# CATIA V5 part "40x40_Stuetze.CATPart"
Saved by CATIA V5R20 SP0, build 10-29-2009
Part number: 40x40_Stuetze
Nomenclature: P40L_N8_I
Source: Unknown
Bounding box of the stored display mesh (mm): x -20 to 20, y -20 to 20, z -150 to 50
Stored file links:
  C:\Users\Andi\Desktop\Offene Projekte\Plasmacutter\Rahmen\40x40_Stuetze.CATPart
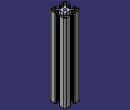
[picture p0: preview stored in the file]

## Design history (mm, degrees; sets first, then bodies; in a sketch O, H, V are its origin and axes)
Set1
  Sketch1 on face of Solid1, origin (0, 0, 150), H (1, 0, 0), V (0, 1, 0)
    projected arc E1 centre (-18.5, 5.5) radius 1.5 from (-20, 5.5) to (-18.5, 4) ccw from edge [face of Solid1 | face of Solid1]
    projected line E2 (-16.5, 4) -> (-18.5, 4) from edge [face of Solid1 | face of Solid1]
    projected arc E3 centre (-16.5, 5) radius 1 from (-16.5, 4) to (-15.5, 5) ccw from edge [face of Solid1 | face of Solid1]
    projected line E4 (-15.5, 6.5) -> (-15.5, 5) from edge [face of Solid1 | face of Solid1]
    projected arc E5 centre (-16, 6.5) radius 0.5 from (-15.5, 6.5) to (-16, 7) ccw from edge [face of Solid1 | face of Solid1]
    projected line E6 (-17.5, 7) -> (-16, 7) from edge [face of Solid1 | face of Solid1]
    projected arc E7 centre (-17.5, 7.5) radius 0.5 from (-18, 7.5) to (-17.5, 7) ccw from edge [face of Solid1 | face of Solid1]
    projected arc E8 centre (-15.5, 7.5) radius 2.5 from (-15.5, 10) to (-18, 7.5) ccw from edge [face of Solid1 | face of Solid1]
    projected line E9 (-14.1924, 10) -> (-15.5, 10) from edge [face of Solid1 | face of Solid1]
    projected arc E10 centre (-14.1924, 5) radius 5 from (-10.6569, 8.5355) to (-14.1924, 10) ccw from edge [face of Solid1 | face of Solid1]
    projected line E11 (-9.2145, 7.0931) -> (-10.6569, 8.5355) from edge [face of Solid1 | face of Solid1]
    projected arc E12 centre (-12.75, 3.5576) radius 5 from (-7.75, 3.5576) to (-9.2145, 7.0931) ccw from edge [face of Solid1 | face of Solid1]
    projected line E13 (-7.75, -3.5576) -> (-7.75, 3.5576) from edge [face of Solid1 | face of Solid1]
    projected arc E14 centre (-12.75, -3.5576) radius 5 from (-9.2145, -7.0931) to (-7.75, -3.5576) ccw from edge [face of Solid1 | face of Solid1]
    projected line E15 (-10.6569, -8.5355) -> (-9.2145, -7.0931) from edge [face of Solid1 | face of Solid1]
    projected arc E16 centre (-14.1924, -5) radius 5 from (-14.1924, -10) to (-10.6569, -8.5355) ccw from edge [face of Solid1 | face of Solid1]
    projected line E17 (-15.5, -10) -> (-14.1924, -10) from edge [face of Solid1 | face of Solid1]
    projected arc E18 centre (-15.5, -7.5) radius 2.5 from (-18, -7.5) to (-15.5, -10) ccw from edge [face of Solid1 | face of Solid1]
    projected arc E19 centre (-17.5, -7.5) radius 0.5 from (-17.5, -7) to (-18, -7.5) ccw from edge [face of Solid1 | face of Solid1]
    projected line E20 (-16, -7) -> (-17.5, -7) from edge [face of Solid1 | face of Solid1]
    projected arc E21 centre (-16, -6.5) radius 0.5 from (-16, -7) to (-15.5, -6.5) ccw from edge [face of Solid1 | face of Solid1]
    projected line E22 (-15.5, -5) -> (-15.5, -6.5) from edge [face of Solid1 | face of Solid1]
    projected arc E23 centre (-16.5, -5) radius 1 from (-15.5, -5) to (-16.5, -4) ccw from edge [face of Solid1 | face of Solid1]
    projected line E24 (-18.5, -4) -> (-16.5, -4) from edge [face of Solid1 | face of Solid1]
    projected arc E25 centre (-18.5, -5.5) radius 1.5 from (-18.5, -4) to (-20, -5.5) ccw from edge [face of Solid1 | face of Solid1]
    projected line E26 (-20, -16) -> (-20, -5.5) from edge [face of Solid1 | face of Solid1]
    projected arc E27 centre (-16, -16) radius 4 from (-20, -16) to (-16, -20) ccw from edge [face of Solid1 | face of Solid1]
    projected line E28 (-5.5, -20) -> (-16, -20) from edge [face of Solid1 | face of Solid1]
    projected arc E29 centre (-5.5, -18.5) radius 1.5 from (-5.5, -20) to (-4, -18.5) ccw from edge [face of Solid1 | face of Solid1]
    projected line E30 (-4, -16.5) -> (-4, -18.5) from edge [face of Solid1 | face of Solid1]
    projected arc E31 centre (-5, -16.5) radius 1 from (-4, -16.5) to (-5, -15.5) ccw from edge [face of Solid1 | face of Solid1]
    projected line E32 (-6.5, -15.5) -> (-5, -15.5) from edge [face of Solid1 | face of Solid1]
    projected arc E33 centre (-6.5, -16) radius 0.5 from (-6.5, -15.5) to (-7, -16) ccw from edge [face of Solid1 | face of Solid1]
    projected line E34 (-7, -17.5) -> (-7, -16) from edge [face of Solid1 | face of Solid1]
    projected arc E35 centre (-7.5, -17.5) radius 0.5 from (-7.5, -18) to (-7, -17.5) ccw from edge [face of Solid1 | face of Solid1]
    projected arc E36 centre (-7.5, -15.5) radius 2.5 from (-10, -15.5) to (-7.5, -18) ccw from edge [face of Solid1 | face of Solid1]
    projected line E37 (-10, -14.1924) -> (-10, -15.5) from edge [face of Solid1 | face of Solid1]
    projected arc E38 centre (-5, -14.1924) radius 5 from (-8.5355, -10.6569) to (-10, -14.1924) ccw from edge [face of Solid1 | face of Solid1]
    projected line E39 (-7.0931, -9.2145) -> (-8.5355, -10.6569) from edge [face of Solid1 | face of Solid1]
    projected arc E40 centre (-3.5576, -12.75) radius 5 from (-3.5576, -7.75) to (-7.0931, -9.2145) ccw from edge [face of Solid1 | face of Solid1]
    projected line E41 (3.5576, -7.75) -> (-3.5576, -7.75) from edge [face of Solid1 | face of Solid1]
    projected arc E42 centre (3.5576, -12.75) radius 5 from (7.0931, -9.2145) to (3.5576, -7.75) ccw from edge [face of Solid1 | face of Solid1]
    projected line E43 (8.5355, -10.6569) -> (7.0931, -9.2145) from edge [face of Solid1 | face of Solid1]
    projected arc E44 centre (5, -14.1924) radius 5 from (10, -14.1924) to (8.5355, -10.6569) ccw from edge [face of Solid1 | face of Solid1]
    projected line E45 (10, -15.5) -> (10, -14.1924) from edge [face of Solid1 | face of Solid1]
    projected arc E46 centre (7.5, -15.5) radius 2.5 from (7.5, -18) to (10, -15.5) ccw from edge [face of Solid1 | face of Solid1]
    projected arc E47 centre (7.5, -17.5) radius 0.5 from (7, -17.5) to (7.5, -18) ccw from edge [face of Solid1 | face of Solid1]
    projected line E48 (7, -16) -> (7, -17.5) from edge [face of Solid1 | face of Solid1]
    projected arc E49 centre (6.5, -16) radius 0.5 from (7, -16) to (6.5, -15.5) ccw from edge [face of Solid1 | face of Solid1]
    projected line E50 (5, -15.5) -> (6.5, -15.5) from edge [face of Solid1 | face of Solid1]
    projected arc E51 centre (5, -16.5) radius 1 from (5, -15.5) to (4, -16.5) ccw from edge [face of Solid1 | face of Solid1]
    projected line E52 (4, -18.5) -> (4, -16.5) from edge [face of Solid1 | face of Solid1]
    projected arc E53 centre (5.5, -18.5) radius 1.5 from (4, -18.5) to (5.5, -20) ccw from edge [face of Solid1 | face of Solid1]
    projected line E54 (16, -20) -> (5.5, -20) from edge [face of Solid1 | face of Solid1]
    projected arc E55 centre (16, -16) radius 4 from (16, -20) to (20, -16) ccw from edge [face of Solid1 | face of Solid1]
    projected line E56 (20, -5.5) -> (20, -16) from edge [face of Solid1 | face of Solid1]
    projected arc E57 centre (18.5, -5.5) radius 1.5 from (20, -5.5) to (18.5, -4) ccw from edge [face of Solid1 | face of Solid1]
    projected line E58 (16.5, -4) -> (18.5, -4) from edge [face of Solid1 | face of Solid1]
    projected arc E59 centre (16.5, -5) radius 1 from (16.5, -4) to (15.5, -5) ccw from edge [face of Solid1 | face of Solid1]
    projected line E60 (15.5, -6.5) -> (15.5, -5) from edge [face of Solid1 | face of Solid1]
    projected arc E61 centre (16, -6.5) radius 0.5 from (15.5, -6.5) to (16, -7) ccw from edge [face of Solid1 | face of Solid1]
    projected line E62 (17.5, -7) -> (16, -7) from edge [face of Solid1 | face of Solid1]
    projected arc E63 centre (17.5, -7.5) radius 0.5 from (18, -7.5) to (17.5, -7) ccw from edge [face of Solid1 | face of Solid1]
    projected arc E64 centre (15.5, -7.5) radius 2.5 from (15.5, -10) to (18, -7.5) ccw from edge [face of Solid1 | face of Solid1]
    projected line E65 (14.1924, -10) -> (15.5, -10) from edge [face of Solid1 | face of Solid1]
    projected arc E66 centre (14.1924, -5) radius 5 from (10.6569, -8.5355) to (14.1924, -10) ccw from edge [face of Solid1 | face of Solid1]
    projected line E67 (9.2145, -7.0931) -> (10.6569, -8.5355) from edge [face of Solid1 | face of Solid1]
    projected arc E68 centre (12.75, -3.5576) radius 5 from (7.75, -3.5576) to (9.2145, -7.0931) ccw from edge [face of Solid1 | face of Solid1]
    projected line E69 (7.75, 3.5576) -> (7.75, -3.5576) from edge [face of Solid1 | face of Solid1]
    projected arc E70 centre (12.75, 3.5576) radius 5 from (9.2145, 7.0931) to (7.75, 3.5576) ccw from edge [face of Solid1 | face of Solid1]
    projected line E71 (10.6569, 8.5355) -> (9.2145, 7.0931) from edge [face of Solid1 | face of Solid1]
    projected arc E72 centre (14.1924, 5) radius 5 from (14.1924, 10) to (10.6569, 8.5355) ccw from edge [face of Solid1 | face of Solid1]
    projected line E73 (15.5, 10) -> (14.1924, 10) from edge [face of Solid1 | face of Solid1]
    projected arc E74 centre (15.5, 7.5) radius 2.5 from (18, 7.5) to (15.5, 10) ccw from edge [face of Solid1 | face of Solid1]
    projected arc E75 centre (17.5, 7.5) radius 0.5 from (17.5, 7) to (18, 7.5) ccw from edge [face of Solid1 | face of Solid1]
    projected line E76 (16, 7) -> (17.5, 7) from edge [face of Solid1 | face of Solid1]
    projected arc E77 centre (16, 6.5) radius 0.5 from (16, 7) to (15.5, 6.5) ccw from edge [face of Solid1 | face of Solid1]
    projected line E78 (15.5, 5) -> (15.5, 6.5) from edge [face of Solid1 | face of Solid1]
    projected arc E79 centre (16.5, 5) radius 1 from (15.5, 5) to (16.5, 4) ccw from edge [face of Solid1 | face of Solid1]
    projected line E80 (18.5, 4) -> (16.5, 4) from edge [face of Solid1 | face of Solid1]
    projected arc E81 centre (18.5, 5.5) radius 1.5 from (18.5, 4) to (20, 5.5) ccw from edge [face of Solid1 | face of Solid1]
    projected line E82 (20, 16) -> (20, 5.5) from edge [face of Solid1 | face of Solid1]
    projected arc E83 centre (16, 16) radius 4 from (20, 16) to (16, 20) ccw from edge [face of Solid1 | face of Solid1]
    projected line E84 (5.5, 20) -> (16, 20) from edge [face of Solid1 | face of Solid1]
    projected arc E85 centre (5.5, 18.5) radius 1.5 from (5.5, 20) to (4, 18.5) ccw from edge [face of Solid1 | face of Solid1]
    projected line E86 (4, 16.5) -> (4, 18.5) from edge [face of Solid1 | face of Solid1]
    projected arc E87 centre (5, 16.5) radius 1 from (4, 16.5) to (5, 15.5) ccw from edge [face of Solid1 | face of Solid1]
    projected line E88 (6.5, 15.5) -> (5, 15.5) from edge [face of Solid1 | face of Solid1]
    projected arc E89 centre (6.5, 16) radius 0.5 from (6.5, 15.5) to (7, 16) ccw from edge [face of Solid1 | face of Solid1]
    projected line E90 (7, 17.5) -> (7, 16) from edge [face of Solid1 | face of Solid1]
    projected arc E91 centre (7.5, 17.5) radius 0.5 from (7.5, 18) to (7, 17.5) ccw from edge [face of Solid1 | face of Solid1]
    projected arc E92 centre (7.5, 15.5) radius 2.5 from (10, 15.5) to (7.5, 18) ccw from edge [face of Solid1 | face of Solid1]
    projected line E93 (10, 14.1924) -> (10, 15.5) from edge [face of Solid1 | face of Solid1]
    projected arc E94 centre (5, 14.1924) radius 5 from (8.5355, 10.6569) to (10, 14.1924) ccw from edge [face of Solid1 | face of Solid1]
    projected line E95 (7.0931, 9.2145) -> (8.5355, 10.6569) from edge [face of Solid1 | face of Solid1]
    projected arc E96 centre (3.5576, 12.75) radius 5 from (3.5576, 7.75) to (7.0931, 9.2145) ccw from edge [face of Solid1 | face of Solid1]
    projected line E97 (-3.5576, 7.75) -> (3.5576, 7.75) from edge [face of Solid1 | face of Solid1]
    projected arc E98 centre (-3.5576, 12.75) radius 5 from (-7.0931, 9.2145) to (-3.5576, 7.75) ccw from edge [face of Solid1 | face of Solid1]
    projected line E99 (-8.5355, 10.6569) -> (-7.0931, 9.2145) from edge [face of Solid1 | face of Solid1]
    projected arc E100 centre (-5, 14.1924) radius 5 from (-10, 14.1924) to (-8.5355, 10.6569) ccw from edge [face of Solid1 | face of Solid1]
    projected line E101 (-10, 15.5) -> (-10, 14.1924) from edge [face of Solid1 | face of Solid1]
    projected arc E102 centre (-7.5, 15.5) radius 2.5 from (-7.5, 18) to (-10, 15.5) ccw from edge [face of Solid1 | face of Solid1]
    projected arc E103 centre (-7.5, 17.5) radius 0.5 from (-7, 17.5) to (-7.5, 18) ccw from edge [face of Solid1 | face of Solid1]
    projected line E104 (-7, 16) -> (-7, 17.5) from edge [face of Solid1 | face of Solid1]
    projected arc E105 centre (-6.5, 16) radius 0.5 from (-7, 16) to (-6.5, 15.5) ccw from edge [face of Solid1 | face of Solid1]
    projected line E106 (-5, 15.5) -> (-6.5, 15.5) from edge [face of Solid1 | face of Solid1]
    projected arc E107 centre (-5, 16.5) radius 1 from (-5, 15.5) to (-4, 16.5) ccw from edge [face of Solid1 | face of Solid1]
    projected line E108 (-4, 18.5) -> (-4, 16.5) from edge [face of Solid1 | face of Solid1]
    projected arc E109 centre (-5.5, 18.5) radius 1.5 from (-4, 18.5) to (-5.5, 20) ccw from edge [face of Solid1 | face of Solid1]
    projected line E110 (-16, 20) -> (-5.5, 20) from edge [face of Solid1 | face of Solid1]
    projected arc E111 centre (-16, 16) radius 4 from (-16, 20) to (-20, 16) ccw from edge [face of Solid1 | face of Solid1]
    projected line E112 (-20, 5.5) -> (-20, 16) from edge [face of Solid1 | face of Solid1]
    projected line E113 (11.8, -17.7) -> (11.8, -12.3) from edge [face of Solid1 | face of Solid1]
    projected arc E114 centre (12.3, -12.3) radius 0.5 from (12.3, -11.8) to (11.8, -12.3) ccw from edge [face of Solid1 | face of Solid1]
    projected line E115 (12.3, -11.8) -> (17.7, -11.8) from edge [face of Solid1 | face of Solid1]
    projected arc E116 centre (17.7, -12.3) radius 0.5 from (18.2, -12.3) to (17.7, -11.8) ccw from edge [face of Solid1 | face of Solid1]
    projected line E117 (18.2, -12.3) -> (18.2, -16) from edge [face of Solid1 | face of Solid1]
    projected arc E118 centre (16, -16) radius 2.2 from (16, -18.2) to (18.2, -16) ccw from edge [face of Solid1 | face of Solid1]
    projected line E119 (16, -18.2) -> (12.3, -18.2) from edge [face of Solid1 | face of Solid1]
    projected arc E120 centre (12.3, -17.7) radius 0.5 from (11.8, -17.7) to (12.3, -18.2) ccw from edge [face of Solid1 | face of Solid1]
    projected line E121 (-17.7, -11.8) -> (-12.3, -11.8) from edge [face of Solid1 | face of Solid1]
    projected arc E122 centre (-12.3, -12.3) radius 0.5 from (-11.8, -12.3) to (-12.3, -11.8) ccw from edge [face of Solid1 | face of Solid1]
    projected line E123 (-11.8, -12.3) -> (-11.8, -17.7) from edge [face of Solid1 | face of Solid1]
    projected arc E124 centre (-12.3, -17.7) radius 0.5 from (-12.3, -18.2) to (-11.8, -17.7) ccw from edge [face of Solid1 | face of Solid1]
    projected line E125 (-12.3, -18.2) -> (-16, -18.2) from edge [face of Solid1 | face of Solid1]
    projected arc E126 centre (-16, -16) radius 2.2 from (-18.2, -16) to (-16, -18.2) ccw from edge [face of Solid1 | face of Solid1]
    projected line E127 (-18.2, -16) -> (-18.2, -12.3) from edge [face of Solid1 | face of Solid1]
    projected arc E128 centre (-17.7, -12.3) radius 0.5 from (-17.7, -11.8) to (-18.2, -12.3) ccw from edge [face of Solid1 | face of Solid1]
    projected line E129 (-11.8, 17.7) -> (-11.8, 12.3) from edge [face of Solid1 | face of Solid1]
    projected arc E130 centre (-12.3, 12.3) radius 0.5 from (-12.3, 11.8) to (-11.8, 12.3) ccw from edge [face of Solid1 | face of Solid1]
    projected line E131 (-12.3, 11.8) -> (-17.7, 11.8) from edge [face of Solid1 | face of Solid1]
    projected arc E132 centre (-17.7, 12.3) radius 0.5 from (-18.2, 12.3) to (-17.7, 11.8) ccw from edge [face of Solid1 | face of Solid1]
    projected line E133 (-18.2, 12.3) -> (-18.2, 16) from edge [face of Solid1 | face of Solid1]
    projected arc E134 centre (-16, 16) radius 2.2 from (-16, 18.2) to (-18.2, 16) ccw from edge [face of Solid1 | face of Solid1]
    projected line E135 (-16, 18.2) -> (-12.3, 18.2) from edge [face of Solid1 | face of Solid1]
    projected arc E136 centre (-12.3, 17.7) radius 0.5 from (-11.8, 17.7) to (-12.3, 18.2) ccw from edge [face of Solid1 | face of Solid1]
    projected line E137 (17.7, 11.8) -> (12.3, 11.8) from edge [face of Solid1 | face of Solid1]
    projected arc E138 centre (12.3, 12.3) radius 0.5 from (11.8, 12.3) to (12.3, 11.8) ccw from edge [face of Solid1 | face of Solid1]
    projected line E139 (11.8, 12.3) -> (11.8, 17.7) from edge [face of Solid1 | face of Solid1]
    projected arc E140 centre (12.3, 17.7) radius 0.5 from (12.3, 18.2) to (11.8, 17.7) ccw from edge [face of Solid1 | face of Solid1]
    projected line E141 (12.3, 18.2) -> (16, 18.2) from edge [face of Solid1 | face of Solid1]
    projected arc E142 centre (16, 16) radius 2.2 from (18.2, 16) to (16, 18.2) ccw from edge [face of Solid1 | face of Solid1]
    projected line E143 (18.2, 16) -> (18.2, 12.3) from edge [face of Solid1 | face of Solid1]
    projected arc E144 centre (17.7, 12.3) radius 0.5 from (17.7, 11.8) to (18.2, 12.3) ccw from edge [face of Solid1 | face of Solid1]
    projected arc E145 centre (0, 0) radius 3.4 from (-3.4, 0) to (3.4, 0) ccw from edge [face of Solid1 | face of Solid1]
    projected arc E146 centre (0, 0) radius 3.4 from (3.4, 0) to (-3.4, 0) ccw from edge [face of Solid1 | face of Solid1]
Body1 "MANIFOLD_SOLID_BREP #5039" (main body)
  Solid1: solid without history
  Pocket1: profile Sketch1, direction (0, 0, -1), length 100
